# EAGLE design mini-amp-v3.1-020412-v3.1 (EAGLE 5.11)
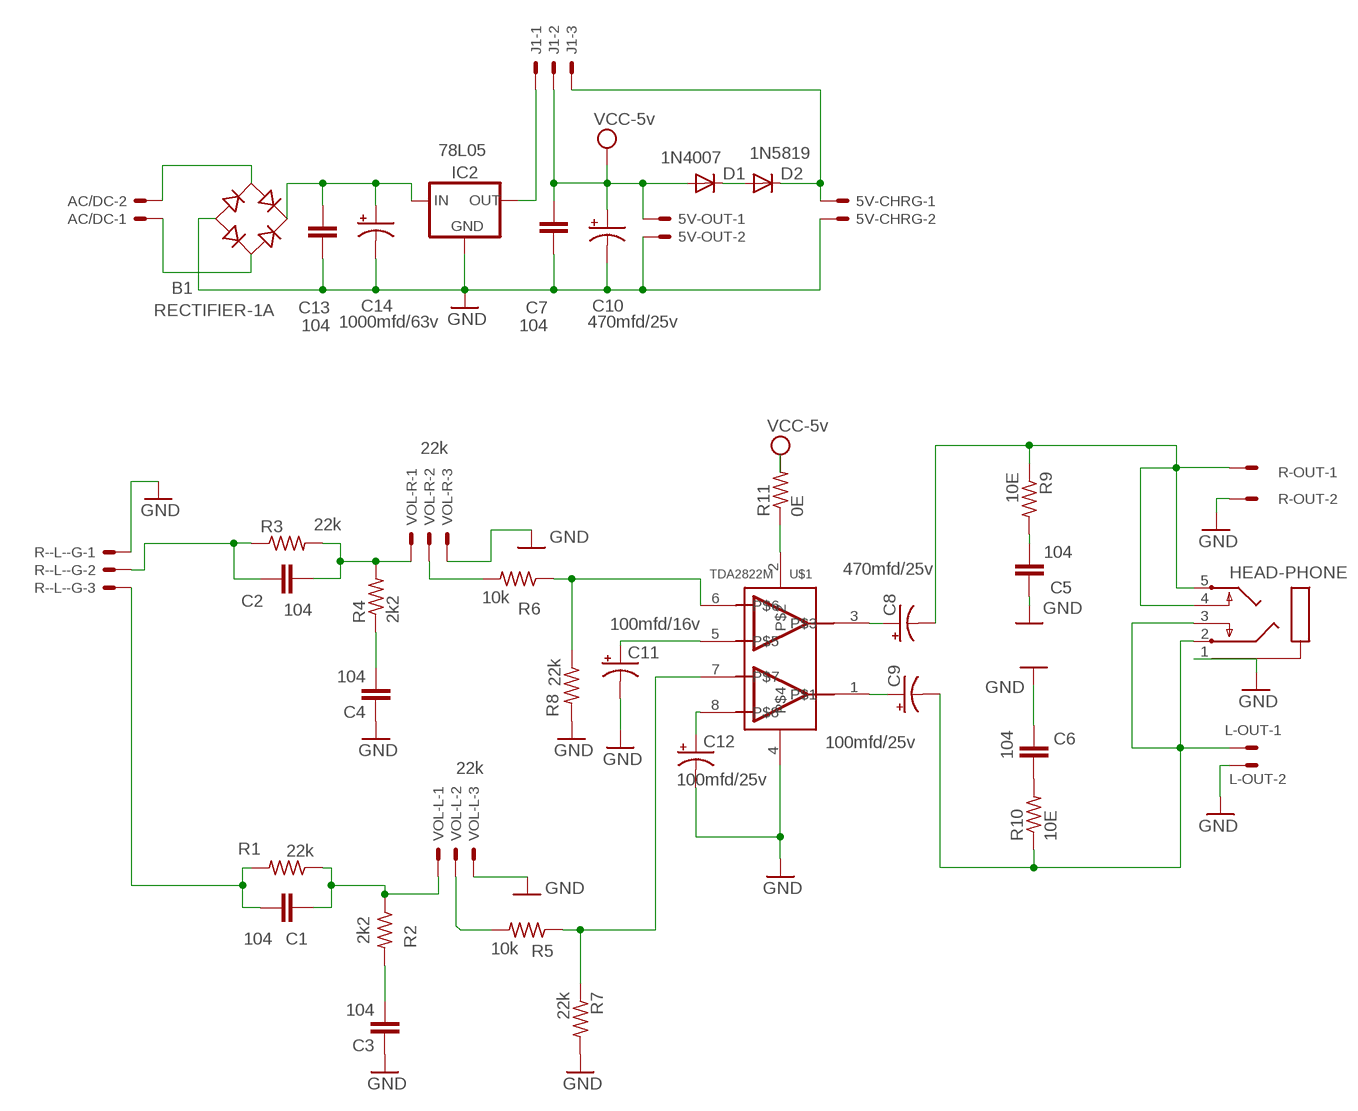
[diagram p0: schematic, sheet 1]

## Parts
5V-CHRG  22-23-2021  [22-23-2021]
5V-OUT  22-23-2021  [22-23-2021]
AC/DC  22-23-2021  [22-23-2021]
B1  RECTIFIER-1A  RECTIFIER-RB1A  [RB1A]
C1  104  C-EU025_050-025X075  [C025_050-025X075]
C2  104  C-EU025_050-025X075  [C025_050-025X075]
C3  104  C-EU025_050-025X075  [C025_050-025X075]
C4  104  C-EU025-025X050  [C025-025X050]
C5  104  C-EU025-025X050  [C025-025X050]
C6  104  C-EU025-025X050  [C025-025X050]
C7  104  C-EU025-025X050  [C025-025X050]
C8  470mfd/25v  CPOL-USE5-8.5  [E5-8,5]
C9  100mfd/25v  CPOL-USE5-8.5  [E5-8,5]
C10  470mfd/25v  CPOL-USTT2D5  [TT2D5]
C11  100mfd/16v  CPOL-USE2-5  [E2-5]
C12  100mfd/25v  CPOL-USE2-5  [E2-5]
C13  104  C-EU025-025X050  [C025-025X050]
C14  1000mfd/63v  CPOL-USE5-8.5  [E5-8,5]
D1  1N4007  DIODE-DO41-10  [DO41-10]
D2  1N5819  DIODE-DO41-10  [DO41-10]
HEAD-PHONE  PG203J  [PG203J]
IC2  78L05  78XXS  [78XXS]
J1  22-27-2031-03  [6410-03]
L-OUT  22-23-2021  [22-23-2021]
R1  22k  R-US_0207/10  [0207/10]
R2  2k2  R-US_0207/10  [0207/10]
R3  22k  R-US_0207/10  [0207/10]
R4  2k2  R-US_0207/10  [0207/10]
R5  10k  R-US_0207/10  [0207/10]
R6  10k  R-US_0207/10  [0207/10]
R7  22k  R-US_0207/10  [0207/10]
R8  22k  R-US_0207/10  [0207/10]
R9  10E  R-US_0207/10  [0207/10]
R10  10E  R-US_0207/10  [0207/10]
R11  0E  R-US_0207/10  [0207/10]
R--L--G  22-23-2031  [22-23-2031]
R-OUT  22-23-2021  [22-23-2021]
U$1  TDA2822M  [DIL08]
VOL-L  47k  22-23-2031  [22-23-2031]
VOL-R  47k  22-23-2031  [22-23-2031]

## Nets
5V: 5V-OUT.1 C7.2 C10.+ D1.A J1.2 R11.2 ; supply symbol labelled VCC-5v
GND: 5V-CHRG.2 5V-OUT.2 B1.- C3.1 C4.1 C5.1 C6.1 C7.1 C10.- C11.- C12.- C13.1 C14.- HEAD-PHONE.1 IC2.GND L-OUT.2 R7.2 R8.2 R--L--G.1 R-OUT.2 U$1.4 VOL-L.3 VOL-R.3
N$1: C1.2 R1.1 R2.1 VOL-L.1
N$2: C1.1 R1.2 R--L--G.3
N$3: C2.1 R3.1 R--L--G.2
N$4: C2.2 R3.2 R4.2 VOL-R.1
N$5: C3.2 R2.2
N$6: C4.2 R4.1
N$7: 5V-CHRG.1 D2.C J1.3
N$8: D1.C D2.A
N$9: R6.2 VOL-R.2
N$10: AC/DC.2 B1.AC1
N$11: AC/DC.1 B1.AC2
N$12: R5.2 VOL-L.2
N$13: B1.+ C13.2 C14.+ IC2.IN
N$14: C12.+ U$1.8
N$15: C8.- HEAD-PHONE.4 HEAD-PHONE.5 R9.1 R-OUT.1
N$16: C9.- HEAD-PHONE.2 HEAD-PHONE.3 L-OUT.1 R10.1
N$17: R5.1 R7.1 U$1.7
N$18: C9.+ U$1.1
N$19: C5.2 R9.2
N$20: C6.2 R10.2
N$21: IC2.OUT J1.1
N$23: C8.+ U$1.3
N$25: C11.+ U$1.5
N$27: R6.1 R8.1 U$1.6
N$28: R11.1 U$1.2

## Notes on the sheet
- 22k
- 22k

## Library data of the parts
5V-CHRG 5V-OUT AC/DC L-OUT R-OUT = con-molex:22-23-2021: .100" (2.54mm) Center Header - 2 Pin; MF: MOLEX; MPN: 22-23-2021; OC_FARNELL: 1462926; OC_NEWARK: 25C3832
B1 = rectifier:RECTIFIER-: Rectifier
C1-C7 C13 = rcl:C-EU: CAPACITOR, European symbol
C8-C12 C14 = rcl:CPOL-US: POLARIZED CAPACITOR, American symbol
D1 D2 = diode:DIODE-: DIODE
HEAD-PHONE = con-hirschmann:PG203J: MIC/HEADPHONE JACK KS-S stereo microphone/headphone jack PG203JN (Schukat); OC_FARNELL: unknown; OC_NEWARK: unknown
IC2 = v-reg:78XXS: VOLTAGE REGULATOR
J1 = con-molex:22-?-03: CONNECTOR wire to board 2.54 mm (.1 inch) pitch header; OC_FARNELL: unknown; OC_NEWARK: unknown
R1-R11 = rcl:R-US_: RESISTOR, American symbol
R--L--G VOL-L VOL-R = con-molex:22-23-2031: .100" (2.54mm) Center Header - 3 Pin; MF: MOLEX; MPN: 22-23-2031; OC_FARNELL: 1462950; OC_NEWARK: 30C0862
U$1 = myowncomp:TDA2822M: stereo opamp IC with dip 8 pin package

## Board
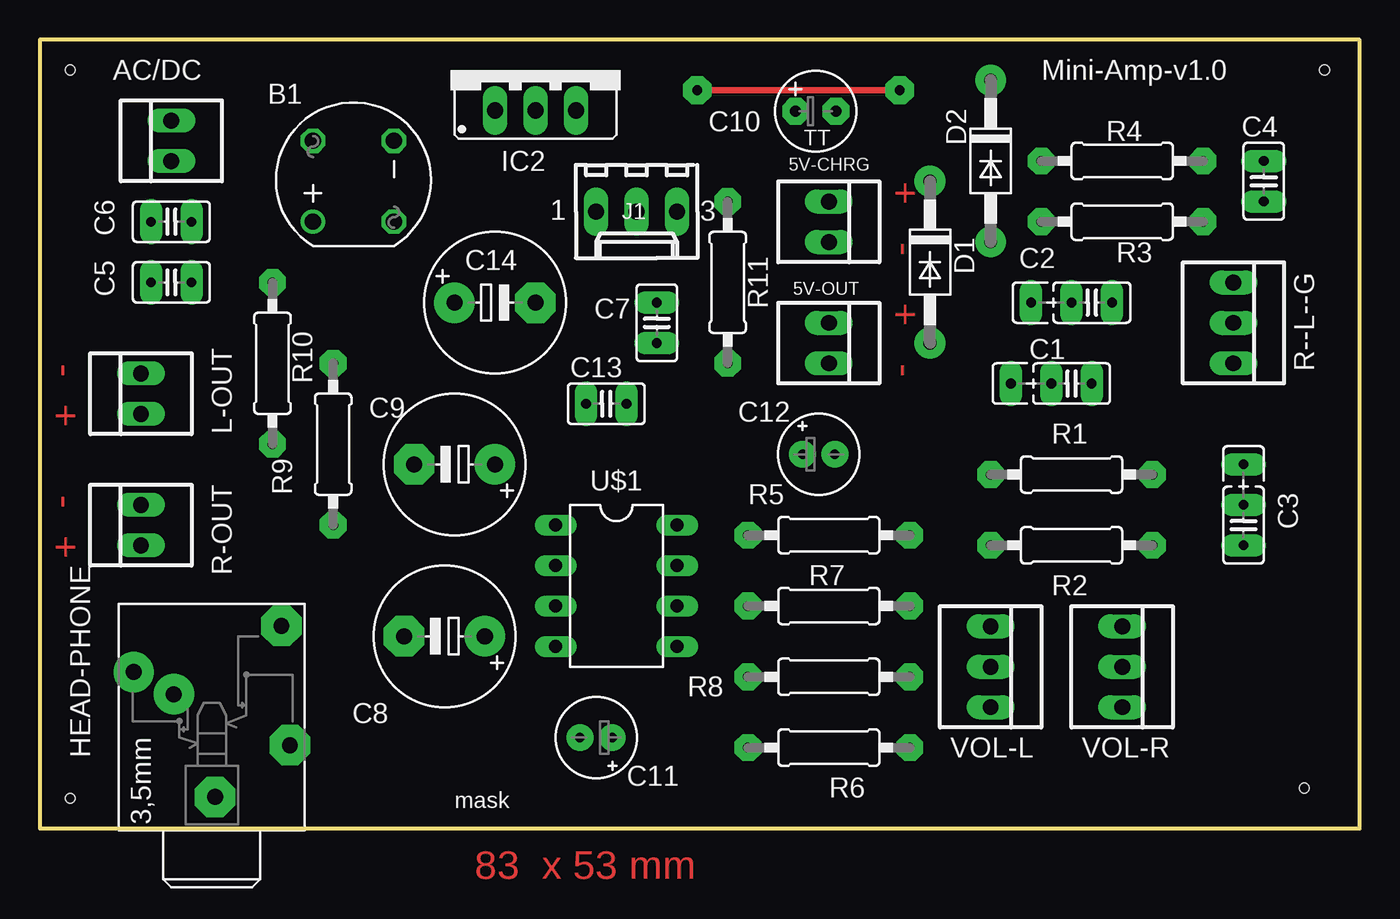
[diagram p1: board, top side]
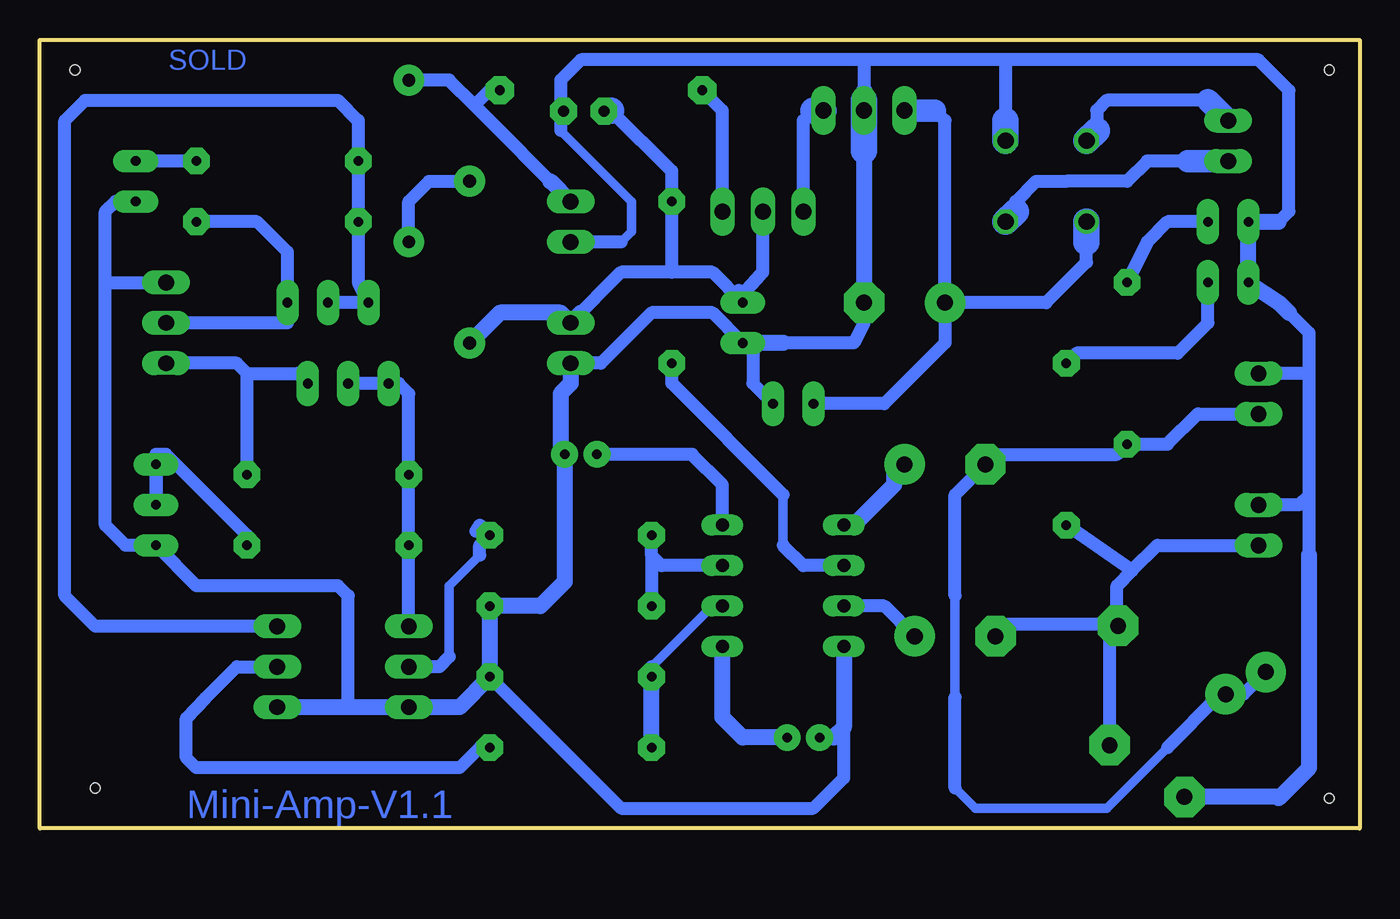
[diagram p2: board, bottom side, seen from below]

Size 82.86 x 49.52 mm. Coordinates in mm from the lower left corner, seen from the top.
Outline: 0,0 82.86,0 82.86,49.52 0,49.52 0,0
Copper layers (1*16): Top 0.035mm / dielectric 1.5mm / Bottom 0.035mm
Design rules "default": minimum track width 10mil, minimum drill 24mil, track to track 8mil, track to pad 8mil, pad to pad 8mil, via to via 8mil, smd to smd 8mil, copper to edge 40mil, drill to drill 8mil, minimum pad ring 10mil, minimum via ring 8mil, stop-mask expansion 4mil, vias tented up to drill 0mil, thermal gap 10mil
Holes 0.6 mm at 79.38,2.54 80.64,47.62 1.91,47.62 1.91,1.91

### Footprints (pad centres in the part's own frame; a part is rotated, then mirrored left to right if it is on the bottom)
22-23-2021 = drill 1 long: 1 -1.27,0; 2 1.27,0
RB1A = drill 1.016 round: + -2.54,2.54 | drill 1.016 octagon: - 2.54,-2.54; AC1 2.54,2.54; AC2 -2.54,-2.54
C025_050-025X075 = drill 0.6 pad 1.422 long: 1 -1.27,0; 2 1.27,0; 3 3.81,0
C025-025X050 = drill 0.6 pad 1.422 long: 1 -1.27,0; 2 1.27,0
E5-8,5 = drill 1.016 pad 2.54 round: + -2.54,0 | drill 1.016 pad 2.54 octagon: - 2.54,0
TT2D5 = drill 0.7 pad 1.676 octagon: + -1.27,0; - 1.27,0
E2-5 = drill 0.6 pad 1.676 round: + -1.016,0; - 1.016,0
DO41-10 = drill 0.8 pad 1.93 round: A 5.08,0; C -5.08,0
PG203J = drill 1 pad 2.54 octagon: 1 -5.004,-0.203; 4 5.74,-4.369; 5 -1.753,-4.902 | drill 1 pad 2.54 round: 2 2.845,4.902; 3 1.448,2.388
78XXS = drill 1.016 long: GND 0,-2.54; IN -2.54,-2.54; OUT 2.54,-2.54
6410-03 = drill 1.016 long: 1 2.54,0; 2 0,0; 3 -2.54,0
0207/10 = drill 0.6 pad 1.676 octagon: 1 -5.08,0; 2 5.08,0
22-23-2031 = drill 1 long: 1 -2.54,0; 2 0,0; 3 2.54,0
DIL08 = drill 0.813 long: 1 -10.16,-3.81; 2 -7.62,-3.81; 3 -5.08,-3.81; 4 -2.54,-3.81; 5 -2.54,3.81; 6 -5.08,3.81; 7 -7.62,3.81; 8 -10.16,3.81

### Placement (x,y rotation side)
5V-CHRG  49.53,38.1 270 top
5V-OUT  49.53,30.48 270 top
AC/DC  8.25,43.18 90 top
B1  19.69,40.64 90 top
C1  64.77,27.94 180 top
C2  66.04,33.02 180 top
C3  75.56,19.05 90 top
C4  76.83,40.64 90 top
C5  8.25,34.29 0 top
C6  8.25,38.1 0 top
C7  38.73,31.75 90 top
C8  25.4,12.06 180 top
C9  26.03,22.86 180 top
C10  48.71,45.04 0 top
C11  34.92,5.72 180 top
C12  48.9,23.5 0 top
C13  35.56,26.67 180 top
C14  28.58,33.02 0 top
D1  55.88,35.56 270 top
D2  59.69,41.91 270 top
HEAD-PHONE  10.79,6.98 90 top
IC2  31.12,47.62 0 top
J1  37.46,38.73 180 top
L-OUT  6.35,27.3 90 top
R1  64.77,22.23 0 top
R2  64.77,17.78 0 top
R3  67.95,38.1 180 top
R4  67.95,41.91 180 top
R5  49.53,18.41 0 top
R6  49.53,5.08 0 top
R7  49.53,13.97 0 top
R8  49.53,9.52 0 top
R9  18.41,24.13 90 top
R10  14.61,29.21 90 top
R11  43.18,34.29 90 top
R--L--G  74.93,31.75 270 top
R-OUT  6.35,19.05 90 top
U$1  36.2,8.89 270 top
VOL-L  59.69,10.16 270 top
VOL-R  67.95,10.16 270 top

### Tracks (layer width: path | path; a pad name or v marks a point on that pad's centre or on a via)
5V
  Bottom 0.813: 43.18,34.92 40.64,34.92 C7.2 38.99,33.78 38.73,33.53 37.59,34.8 37.46,34.92 J1.2 | 43.18,34.92 46.35,34.92 5V-OUT.1 | 46.99,45.08 43.18,41.28 R11.2 43.18,34.92
  Bottom 1.016: 47.44,44.9 C10.+ 47.39,45.08 | 48.89,32.39 5V-OUT.1 50.16,32.39 53.98,32.39 D1.A
  Bottom 1.676: 46.99,45.08 47.39,45.08
GND
  Bottom 0.61: 46.35,36.83 45.72,37.47 45.72,39.37 50.16,43.81
  Bottom 0.813: 22.23,48.26 6.35,48.26 4.45,46.36 4.45,38.73 5.08,38.1 | U$1.4 32.38,3.17 34.29,1.27 46.35,1.27 R8.2 | 63.5,7.62 63.5,14.6 64.14,15.24 73.02,15.24 C3.1 77.47,17.78 78.74,19.05 78.74,34.29 | C13.1 38.1,27.94 38.1,30.48 | C4.1 78.11,39.37 78.74,38.73 78.74,34.29 | 5V-OUT.2 47.62,29.21 44.45,32.39 40.64,32.39 C7.1 | 31.12,48.26 48.89,48.26 50.16,46.99 50.16,45.22 C10.- 50.16,44.86 50.16,43.81 | 31.12,48.26 31.12,45.72 | 46.35,36.83 5V-CHRG.2 | 78.74,34.29 R--L--G.1 | 3.17,17.15 3.17,20.95 | 3.17,20.95 3.17,28.58 | 3.17,28.58 3.17,31.12 4.45,32.39 | 3.17,28.58 L-OUT.2 | R-OUT.2 3.81,20.32 3.17,20.95 | 22.23,48.26 22.23,44.45 | 22.23,48.26 31.12,48.26 | 31.12,33.66 C14.- 31.12,31.75 31.75,30.48 36.2,30.48
  Bottom 1.016: 31.12,42.55 31.12,33.66 | 31.12,45.72 31.12,46.36 | 4.45,32.39 5.08,33.02 C5.1 C6.1 5.08,38.1 | HEAD-PHONE.1 5.16,1.98 5.08,1.91 3.17,3.81 3.17,17.15 | 36.2,30.48 38.1,30.48 C7.1 | 5V-OUT.2 49.53,27.94 50.16,27.3 50.16,23.75 C12.- 49.91,15.49 51.43,13.97 R7.2 R8.2 56.52,7.62 VOL-L.3 63.5,7.62 VOL-R.3 | C11.- 33.02,5.72 32.38,6.35 U$1.4
  Bottom 1.676: 31.12,42.55 IC2.GND 31.12,45.72 | 22.23,44.45 B1.-
N$1
  Bottom 0.813: VOL-L.1 R2.1 R1.1 59.69,27.3 60.32,27.94 C1.2
N$2
  Bottom 0.813: R--L--G.3 70.48,29.21 69.85,28.58 | R1.2 69.85,28.58 | 69.85,28.58 66.67,28.58 C1.1
N$3
  Bottom 0.813: R3.1 69.22,38.1 67.31,36.19 C2.1 67.31,31.75 R--L--G.2
N$4
  Bottom 0.813: C2.2 62.23,33.02 62.86,34.29 R3.2 R4.2 62.86,44.45 64.14,45.72 80.01,45.72 81.28,44.45 81.28,14.6 79.38,12.7 VOL-R.1
N$5
  Bottom 0.813: R2.2 69.85,18.41 74.93,23.49 75.56,23.49 C3.2 75.56,22.86
N$6
  Bottom 0.813: R4.1 C4.2
N$7  (via drill 0.6 pad 1.78)
  Top 0.406: v41.27,46.36 v53.98,46.36
  Bottom 0.813: 55.56,45.4 5V-CHRG.1 | 55.56,45.4 57.15,46.99 D2.C | v53.98,46.36 54.61,46.36 55.56,45.4 | J1.3 40,45.08 v41.27,46.36
  Bottom 1.016: 5V-CHRG.1 50.8,40.64
N$8
  Bottom 0.813: D1.C 58.42,40.64 59.69,39.37 D2.A
N$9
  Bottom 0.813: 67.31,10.16 VOL-R.2 70.48,10.16 72.46,8.19 73.66,6.92 73.66,4.45 73.02,3.81 56.52,3.81 55.24,5.08 R6.2
N$10
  Bottom 0.813: 9.53,45.72 15.88,45.72 16.51,45.08 16.51,43.81
  Bottom 1.422: AC/DC.2 9.53,45.72
  Bottom 1.676: 16.51,43.81 B1.AC1
N$11
  Bottom 0.813: 21.59,38.73 21.59,39.37 20.32,40.64 19.69,40.64 18.41,40.64 14.61,40.64 13.34,41.91 10.79,41.91
  Bottom 1.422: AC/DC.1 10.79,41.91
  Bottom 1.676: B1.AC2 21.59,38.73
N$12
  Bottom 0.61: 57.15,10.8 57.15,15.24 55.24,17.15
  Bottom 0.813: 55.49,18.66 55.24,19.05 R5.2 55.24,17.78 55.24,17.15 | 57.15,10.8 57.78,10.16 VOL-L.2
N$13
  Bottom 0.813: C13.2 29.84,26.67 26.03,30.48 C14.+ | B1.+ 17.14,35.56 19.69,33.02 C14.+ | C14.+ 26.03,44.45 26.67,45.08
  Bottom 1.422: 26.67,45.08 IC2.IN
  Bottom 1.676: B1.+ 17.14,36.83
N$14
  Bottom 0.813: C12.+ 41.91,23.5 40,21.59 U$1.8
N$15
  Bottom 0.813: 15.85,5.08 HEAD-PHONE.5 15.7,12.19 HEAD-PHONE.4 | R-OUT.1 12.7,17.78 14.29,16.19 | 14.29,16.19 15.24,15.24 15.24,12.8 22.12,12.8 C8.- | 14.29,16.19 R9.1
  Bottom 1.016: HEAD-PHONE.4 15.24,12.8
N$16
  Bottom 0.61: 12.07,5.08 15.88,1.27 24.13,1.27 25.4,2.54 | 25.4,8.26 25.4,14.6
  Bottom 0.813: 25.4,2.54 25.4,8.26 | 12.07,5.08 8.89,8.26 8.59,8.26 HEAD-PHONE.3 7.29,8.43 HEAD-PHONE.2 | L-OUT.1 10.16,26.03 12.07,24.13 R10.1 15.24,23.49 22.86,23.49 C9.- 25.4,20.95 25.4,14.6
N$17
  Bottom 0.813: 44.45,17.15 R7.1 | 44.45,17.15 R5.1 | U$1.7 43.81,16.51 44.45,17.15
N$18
  Bottom 1.016: U$1.1 31.75,19.05 29.21,21.59 29.21,22.23 C9.+
N$19
  Bottom 0.813: C5.2 9.53,31.75 11.43,29.84 17.78,29.84 R9.2
N$20
  Bottom 0.813: C6.2 12.07,38.1 13.34,36.83 R10.2
N$21
  Bottom 0.813: 34.29,45.08 34.92,44.45 J1.1
  Bottom 1.676: 34.29,45.08 IC2.OUT
N$23
  Bottom 0.813: C8.+ 29.84,13.97 U$1.3
N$25
  Bottom 1.016: U$1.5 40,6.98 38.73,5.72 C11.+
N$27
  Bottom 0.61: 44.45,10.16 40.64,13.97
  Bottom 0.813: 40.64,13.97 U$1.6 | 44.45,8.89 44.45,10.16
  Bottom 1.016: R6.1 44.45,8.89 R8.1
N$28
  Bottom 0.61: 36.2,17.78 36.2,20.95
  Bottom 0.813: R11.1 43.18,27.94 36.2,20.95 | 36.2,17.78 34.92,16.51 U$1.2

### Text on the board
Top: + | - | + | - | - | + | - | + | 83 x 53 mm
Bottom: SOLD | Mini-Amp-V1.1
tNames: Mini-Amp-v1.0 | mask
